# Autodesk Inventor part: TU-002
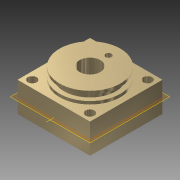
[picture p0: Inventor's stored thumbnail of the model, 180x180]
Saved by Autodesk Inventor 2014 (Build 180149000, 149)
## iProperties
Created: 2008-05
Part Number: TU-002
Document SubType Name: Modeling
Designer: PN
Density: 7.86 g/cm^3
Material: Steel, Mild
Description: Cylinder Head Cover_Front
Mass: 394.415 g
Surface Area: 129.648 cm^2
Volume: 50.1801 cm^3
Appearance: Titanium - Polished
Author: PN
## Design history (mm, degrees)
sketch "Sketch1"
  geometry: L1 (-24.5, 24.5)-(24.5, 24.5); L2 (24.5, 24.5)-(24.5, -24.5); L3 (24.5, -24.5)-(-24.5, -24.5); L4 (-24.5, -24.5)-(-24.5, 24.5); 3 further points
  constraints: 8 end point, 2 midpoint, 2 parallel, 1 horizontal, 1 horizontal alignment, 1 perpendicular, 1 vertical alignment
  dimensions: "Width" = 49 distance of L1.start L1.end; "Height" = 49 distance of L3.end L1.start (= Width)
extrude "Extrusion1" new body sketch "Sketch1" distance "d2" = 20; taper "d3" = 0 deg
sketch "Sketch2"
  geometry: L1 (24.5, 24.5)-(24.5, -24.5) reference; L2 (-24.5, 24.5)-(24.5, 24.5) reference; L3 (-24.5, -24.5)-(-24.5, 24.5) reference; L4 (24.5, -24.5)-(-24.5, -24.5) reference; L5 (19.5, 19.5)-(19.5, -19.5); L6 (19.5, -19.5)-(-19.5, -19.5); L7 (-19.5, -19.5)-(-19.5, 19.5); L8 (-19.5, 19.5)-(19.5, 19.5); 1 further point
  constraints: 8 end point, 3 other
  dimensions: "d4" = 5 distance between parallel lines of L7 L3; "d5" = 39 distance of L5.end L6.end (derived); "d6" = 39 distance of L6.end L7.end (derived)
hole "Hole1" sketch "Sketch2" at (-19.5, -19.5) diameter "d7" = 6; stored, may be unused: countersink angle "d11" = 90 deg, drill point angle "d13" = 118 deg; dims "d8" = 6, "d9" = 4, "d10" = 2, "d12" = 8
pattern_linear "Rectangular Pattern1" dims "d16" = 39 (= d5), "d19" = 39 (= d6)
sketch "Sketch3"
  geometry: L1 (-24.5, 20)-(24.5, 20) reference; L2 (0, 20)-(0, 28); L3 (0, 28)-(20.5, 28); L4 (20.5, 28)-(20.5, 26); L5 (20.5, 26)-(17.5, 26); L6 (17.5, 26)-(17.5, 22); L7 (17.5, 22)-(20.5, 22); L8 (20.5, 22)-(20.5, 20); 1 further point
  constraints: 14 end point, 4 perpendicular, 2 collinear, 2 parallel, 1 midpoint, 1 point on line
  dimensions: "d25" = 8 distance of L2.start L2.end; "d26" = 20.5 distance of L2.end L3.end; "d27" = 2 distance of L3.end L4.end; "d28" = 4 distance of L5.end L6.end; "d29" = 17.5 distance between parallel lines of L6 L2
revolve "Revolution1" sketch "Sketch3" stored, may be unused: angle "d30" = 90 deg
sketch "Sketch4"
  geometry: L1 (0, -20)-(49, -20) reference; L2 (0, 0)-(0, -20) reference; L3 (24.5, -20)-(24.5, -10); 1 further point
  constraints: 2 end point, 1 midpoint, 1 parallel
  dimensions: "d31" = 10 distance of L3.start L3.end
hole "Hole4" sketch "Sketch4" at (24.5, -10) diameter "d48" = 4.134; stored, may be unused: countersink angle "d52" = 90 deg, drill point angle "d54" = 118 deg; dims "d49" = 6, "d50" = 4, "d51" = 2, "d53" = 14
workplane "Work Plane3"
  workaxis "Work Axis2"
sketch "Sketch7"
  geometry: L1 (0, 0)-(0, 12.5); C1 r 20.5 at (0, 0) reference; 1 further point
  constraints: 2 end point, 1 coincident, 1 vertical
  dimensions: "d56" = 12.5 distance of L1.start L1.end
hole "Hole5" sketch "Sketch7" at (0, 12.5) diameter "d57" = 4; stored, may be unused: countersink angle "d61" = 90 deg, drill point angle "d63" = 118 deg; dims "d58" = 6, "d59" = 4, "d60" = 2, "d62" = 14
hole "Hole6" diameter "d66" = 14; stored, may be unused: countersink angle "d70" = 90 deg, drill point angle "d72" = 118 deg; dims "d64" = 10, "d65" = 10, "d67" = 6, "d68" = 4, "d69" = 2, "d71" = 14
body "Solid1"
other parameters: "d55" = 0
